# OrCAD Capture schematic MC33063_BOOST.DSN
size A
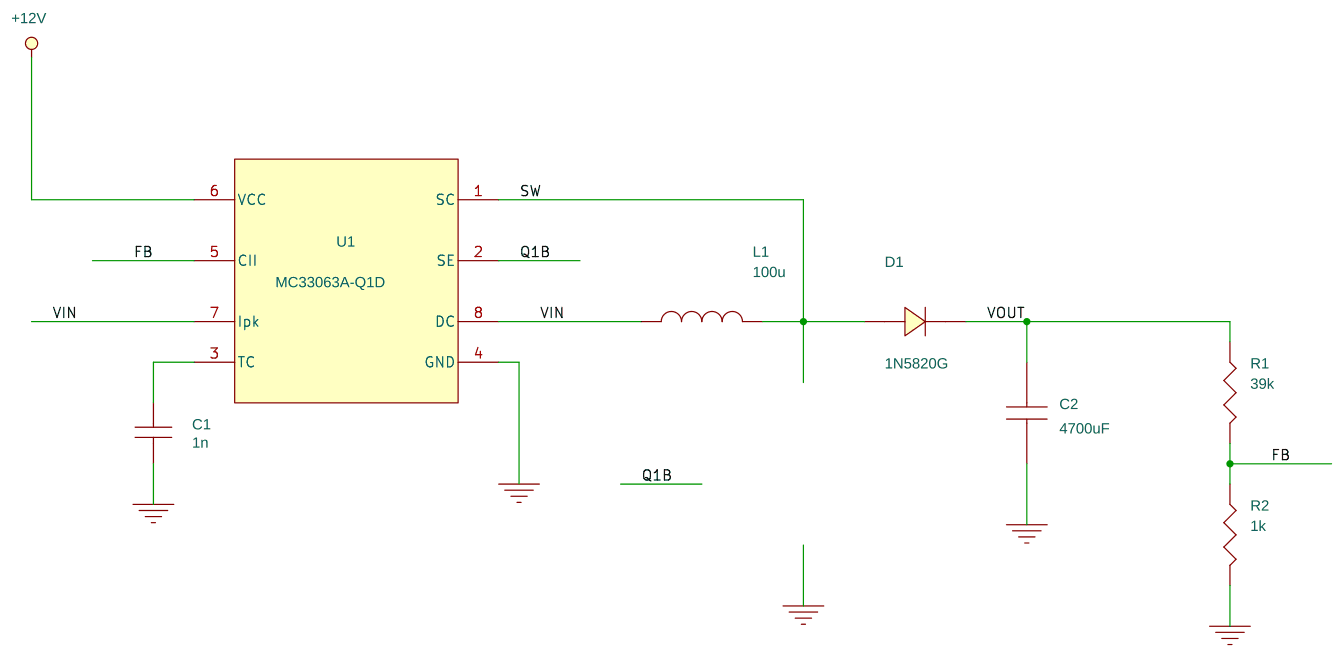
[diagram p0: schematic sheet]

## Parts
C1  1n  [SMC0603]
C2  4700uF  [CAPPRD1250W100D2550H4200]
D1  1N5820G  [DO201AD]
L1  100u  [INDPM125125X800N]
R1  39k  [SMR0603]
R2  1k  [SMR0603]
U1  MC33063A-Q1D  [D0008A_N]

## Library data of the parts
C1 = CAP_NP
C2 = UVR1J472MRD6: Manufacturer Name: Nichicon; Source Id: SamacSys
D1 = DIODE
L1 = DR127-101-R_0: Manufacturer Name: Eaton; Manufacturer Part Number: DR127-101-R; Part Number: DR127-101-R; Source Id: SamacSys
R1 R2 = RESISTOR
U1 = MC33063AQDRQ1: Manufacturer Name: Texas Instruments; Source Id: UL

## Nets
+12V: U1.6(VCC)
VIN: L1.1 U1.7(Ipk) U1.8(DC)
0: C1.2 C2.2(-) R2.2 U1.4(GND)
FB: R1.2 R2.1 U1.5(CII)
Q1B: U1.2(SE)
SW: D1.2(A) L1.2 U1.1(SC)
VOUT: C2.1(+) D1.1(K) R1.1
N00183: C1.1 U1.3(TC)
